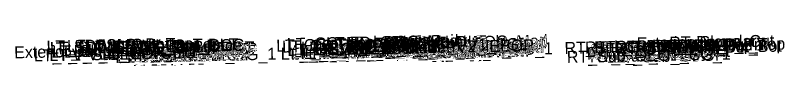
# Model space of a CAD drawing. Extents: x 118 to 4243, y 0 to 9511.
# Drawn here: x 1131.8 to 1260.3, y 3999.5 to 4004.9 of the extents above; entities that cross this region are included whole.
import ezdxf

# ---------------------------------------------------------------- set-up
doc = ezdxf.new("R2010")
doc.units = 0
doc.layers.add('Scratch_Level_0', color=7, linetype='Continuous')

msp = doc.modelspace()

# ---------------------------------------------------------------- texts
at = {"layer": 'Scratch_Level_0'}
for s, p in [('LT_SDWK_Out_Top', (1137.01, 4001.77)), ('LT_SDWK_Out_Bot', (1137.04, 4001.44)), ('LT_Sub_Trench_Out_DLT', (1137.57, 4001.53)), ('LT_CSLP_Pnt', (1140.44, 4001.85)), ('LT_SDWK_In_Top', (1143.63, 4001.71)), ('LT_SDWK_In_Bot', (1143.66, 4001.37)), ('LT_CG_Top_Face', (1147.53, 4001.61)), ('LT_CG_Top_BOC', (1148.05, 4001.63)), ('LT_CG_Top_Face_Med', (1175.39, 4001.91)), ('LT_CG_Top_Gut_Med', (1176.37, 4001.76)), ('LT_CG_Top_BOC_Med', (1177.18, 4002.18)), ('LT_CG_Bot_BOC_Med', (1177.21, 4001.2)), ('LT_CG_Bot_IE_Med', (1177.34, 4001.2)), ('LT_PV2_IEEOP', (1179.53, 4001.57)), ('LT_CG1_Shelf_In', (1181.46, 4001.28)), ('LT_PV2_PGL', (1182.48, 4001.63)), ('LT_PV1_PGL', (1183.05, 4001.9)), ('LT_Sub_DLT_In', (1183.73, 4002.31)), ('MD_Crown Point', (1187.09, 4002.38)), ('RT_CG_Top_Face_Med', (1191.35, 4001.91)), ('RT_CG_Top_BOC_Med', (1191.61, 4002.18)), ('RT_CG_Bot_BOC_Med', (1191.64, 4001.19)), ('RT_CG_Top_Gut_Med', (1192.32, 4001.76)), ('RT_Sub_DLT_In', (1194.15, 4002.31)), ('RT_CG_Bot_IE_Med', (1194.79, 4001.2)), ('RT_CG1_Shelf_In', (1194.89, 4001.28)), ('RT_PV2_OEEOP', (1198.03, 4001.6)), ('RT_PV2_IEEOP', (1198.68, 4001.61)), ('RT_PV2_PGL', (1199.94, 4001.63)), ('RT_PV1_PGL', (1200.5, 4001.89)), ('RT_Sub_Trench_Out_DLT', (1223.56, 4001.53)), ('RT_CG_Top_Face', (1226.99, 4001.6)), ('RT_CG_Top_BOC', (1228.51, 4001.62)), ('RT_SDWK_In_Top', (1232.08, 4001.71)), ('RT_SDWK_In_Bot', (1232.11, 4001.37)), ('RT_SDWK_Out_Top', (1235.46, 4001.77)), ('RT_SDWK_Out_Bot', (1235.49, 4001.44)), ('Exterior Boundary', (1235.62, 4002.3)), ('RT_CSLP_Pnt', (1239.9, 4001.85)), ('RT_Slope_Cut', (1241.07, 4002.41)), ('Exterior Boundary', (1131.6, 4000.8)), ('LT_PV_Sub_Tie_Out', (1134.88, 4000.28)), ('LT_PV_OEEOP_EG', (1137.48, 4000.33)), ('LT_Slope_Fill', (1137.98, 4000.92)), ('LT_CG1_Shelf_Out', (1145.82, 4000.57)), ('LT_CG_Bot_BOC', (1148.09, 4000.61)), ('LT_Sub_OEOT_CG_1', (1148.49, 4000.04)), ('LT_CG_Top_Gut', (1148.51, 4001.12)), ('LT_Sub_OEEOP', (1151.48, 4000.1)), ('LT_PV2_OEEOP', (1151.58, 4001.02)), ('LT_PV3_OEEOP', (1151.58, 4000.68)), ('LT_CG_Bot_IE', (1152.19, 4000.69)), ('LT_Sub_OEOT', (1152.35, 4000.11)), ('LT_PV2_OEOT', (1152.45, 4001.03)), ('LT_PV3_OEOT', (1152.45, 4000.7)), ('LT_PV1_OEOT', (1153.01, 4001.29)), ('LT_PV_Sub_Tie_In', (1176.14, 4000.55)), ('LT_PV_IEEOP_EG', (1177.76, 4000.58)), ('LT_Sub_IEOT_CG_1', (1178.14, 4000.96)), ('LT_Sub_IEEOP', (1179.43, 4000.66)), ('LT_PV3_IEEOP', (1179.53, 4001.24)), ('LT_Sub_PGL', (1182.39, 4000.72)), ('LT_PV3_PGL', (1182.48, 4001.3)), ('LT_Sub_IEOP', (1184.28, 4001.09)), ('RT_Sub_IEOT_CG_1', (1195.59, 4000.96)), ('RT_Sub_IEOP', (1197.23, 4001.09)), ('RT_Sub_OEEOP', (1197.94, 4000.68)), ('RT_PV3_OEEOP', (1198.03, 4001.26)), ('RT_Sub_IEEOP', (1198.58, 4000.69)), ('RT_Sub_PGL', (1199.84, 4000.71)), ('RT_Sub_OEOT_CG_1', (1223.95, 4000.04)), ('RT_CG1_Shelf_Out', (1227.28, 4000.57)), ('RT_CG_Bot_IE', (1227.64, 4000.69)), ('RT_Sub_OEOT', (1227.8, 4000.11)), ('RT_PV2_OEOT', (1227.9, 4001.03)), ('RT_PV3_OEOT', (1227.9, 4000.7)), ('RT_CG_Top_Gut', (1227.96, 4001.12)), ('RT_PV1_OEOT', (1228.46, 4001.29)), ('RT_CG_Bot_BOC', (1228.54, 4000.61)), ('LT_Sub_OEOP', (1148.79, 4000.04)), ('RT_Sub_OEOP', (1231.43, 4000.04))]:
    msp.add_text(s, height=2, rotation=1.1458, dxfattribs=at).set_placement(p)

doc.saveas('drawing.dxf')
